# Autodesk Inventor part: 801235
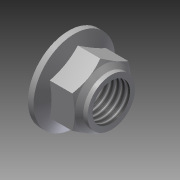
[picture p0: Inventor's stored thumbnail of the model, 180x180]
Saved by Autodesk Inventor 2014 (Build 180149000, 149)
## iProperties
Created: 2007-10
Part Number: 801235
Document SubType Name: Modeling
Designer: TH
Density: 7.86 g/cm^3
Mass: 12.3393 g
Surface Area: 14.5331 cm^2
Volume: 1.56989 cm^3
Material: Steel, Mild
Description: NUT R2456 - M12
Appearance: Steel
Component Category: Fasteners
Author: TH
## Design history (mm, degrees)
sketch "Sketch2"
  geometry: L1 (-7.5, 4.33)-(0, 8.66); L2 (0, 8.66)-(7.5, 4.33); L3 (7.5, 4.33)-(7.5, -4.33); L4 (7.5, -4.33)-(0, -8.66); L5 (0, -8.66)-(-7.5, -4.33); L6 (-7.5, -4.33)-(-7.5, 4.33); L7 (0, 12.124)-(0, -12.124) reference; C1 r 5 at (0, 0); 2 further points
  constraints: 12 end point, 2 coincident, 1 centre point, 1 parallel, 13 other
  dimensions: "d0" = 15 distance between parallel lines of L6 L3; "d1" = 10 diameter of C1
extrude "Extrusion1" new body sketch "Sketch2" distance "d2" = 11.4; taper "d3" = 0 deg
sketch "Sketch3"
  geometry: L1 (0, 10.9)-(0, -10.9) reference; L2 (0, -10.9)-(0, -5); L3 (0, -10.9)-(1.5, -10.9); L4 (1.5, -10.9)-(3.944, -5); L5 (3.944, -5)-(0, -5); L6 (-2.28, 0)-(13.68, 0) reference; 1 further point
  constraints: 8 end point, 2 perpendicular, 1 point on line
  dimensions: "d4" = 1.5 distance of L1.end L3.end; "d5" = 22.5 deg angle of L1 L4; "d6" = 5 distance from line of point (0, 0) L5
revolve "Revolution1" sketch "Sketch3" stored, may be unused: angle "d7" = 90 deg
sketch "Sketch4"
  geometry: L1 (-11.4, 4.33)-(-11.4, 8.66) reference; L2 (-11.4, 6.36)-(-10.26, 6.36); L3 (-10.26, 6.36)-(-9.12, 7.5); L4 (-9.12, 7.5)-(-8.046, 9.36); L5 (-8.046, 9.36)-(-11.4, 9.36); L6 (-11.4, 9.36)-(-11.4, 6.36); L7 (-9.12, 7.5)-(-10.26, 6.36) reference; L8 (-8.45, 8.66)-(-9.12, 7.5) reference; L9 (2.28, 0)-(-13.68, 0) reference; 1 further point
  constraints: 14 end point, 2 perpendicular, 1 parallel, 1 point on line, 6 other
  dimensions: "d8" = 135 deg angle of L2 L3; "d9" = 1.14 distance of L2.start L2.end; "d10" = 6.36 distance from line of point (0, 0) L2; "d11" = 120 deg angle of L2 L4; "d12" = 2.28 distance from line of L3.end L1; "d13" = 3 distance of L5.end L2.start
revolve "Revolution2" sketch "Sketch4" stored, may be unused: angle "d14" = 90 deg
thread "Thread1" dims "d15" = 10, "d16" = 0
body "Solid1"
node "Reference6"
